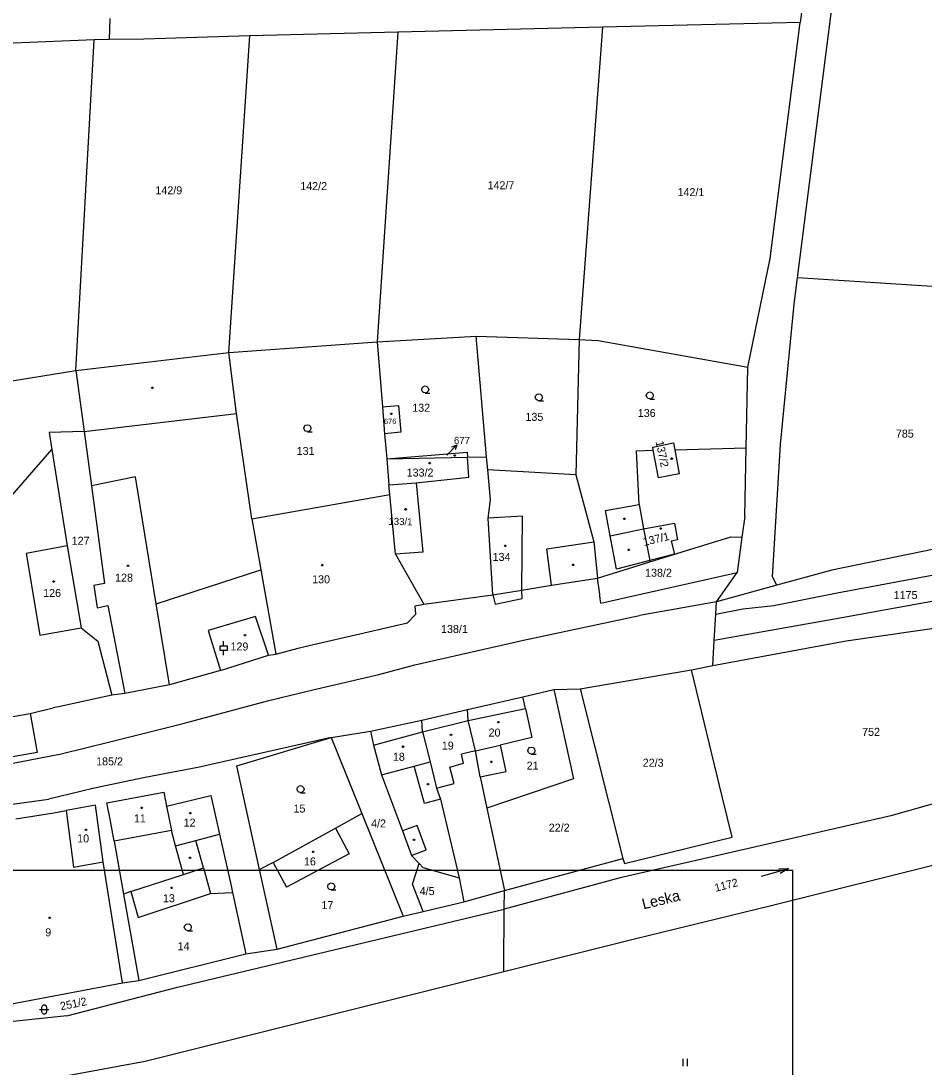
# Model space of a CAD drawing. Extents: x -812394 to -807601, y -1013097 to -1009266.
# Drawn here: x -809610.1 to -809418.3, y -1010812.8 to -1010590.6 of the extents above; entities that cross this region are included whole.
import ezdxf

# ---------------------------------------------------------------- set-up
doc = ezdxf.new("R2010")
doc.units = 0
for name, color, linetype in [('Default', 7, 'Continuous'), ('KN_HRANICE', 7, 'Continuous'), ('KN_KULTURY', 7, 'Continuous'), ('KN_PARCELY', 7, 'Continuous'), ('KN_SLUCKY', 7, 'Continuous'), ('LEGENDA', 7, 'Continuous')]:
    doc.layers.add(name, color=color, linetype=linetype)

# ---------------------------------------------------------------- blocks, each defined once
blk = doc.blocks.new('10292')
at = {"layer": 'Default'}
blk.add_line((0, 3), (0, 0), dxfattribs=at)
blk.add_lwpolyline([(-0.5, 2), (0, 3), (0.5, 2)], dxfattribs=at)
blk = doc.blocks.new('304')
at = {"layer": 'Default'}
blk.add_lwpolyline([(0, 0), (-0.38, 0.1), (-0.65, 0.37), (-0.75, 0.74), (-0.65, 1.11), (-0.38, 1.38), (-0.01, 1.48), (0.36, 1.38), (0.63, 1.11), (0.73, 0.73), (0.63, 0.35), (0.36, 0.08), (-0.02, -0.02), (0.98, -0.02)], dxfattribs=at)
blk = doc.blocks.new('306')
at = {"layer": 'Default'}
for p, q in [((-0.5, 1.5), (-0.5, 0)), ((0.5, 0), (0.5, 1.5))]:
    blk.add_line(p, q, dxfattribs=at)
blk = doc.blocks.new('316')
at = {"layer": 'Default'}
for points in [[(-1, 1), (0.27, 1), (1, 1)], [(-0.5, 1.5), (-0.4, 1.79), (-0.15, 1.97), (0.16, 1.97), (0.41, 1.79), (0.51, 1.5), (0.51, 0.5), (0.41, 0.21), (0.16, 0.03), (-0.15, 0.03), (-0.4, 0.21), (-0.5, 0.5), (-0.5, 1.5)]]:
    blk.add_lwpolyline(points, dxfattribs=at)
blk = doc.blocks.new('NAHRADNI_SYMBOL')
at = {"layer": 'Default'}
blk.add_lwpolyline([(0.09, 0.15), (0.18, 0), (0.09, -0.15), (-0.09, -0.15), (-0.18, 0), (-0.09, 0.15), (0.09, 0.15)], dxfattribs=at)
blk = doc.blocks.new('802')
at = {"layer": 'Default'}
blk.add_line((-3, 0), (3, 0), dxfattribs=at)
blk.add_lwpolyline([(1, 0.5), (3, 0), (1, -0.5)], dxfattribs=at)
blk = doc.blocks.new('318')
at = {"layer": 'Default'}
blk.add_line((0, 2), (0, 3), dxfattribs=at)
blk.add_lwpolyline([(0, 0), (0, 1), (-0.75, 1), (-0.75, 2), (0, 2), (0.75, 2), (0.75, 1), (0, 1)], dxfattribs=at)
blk = doc.blocks.new('402')
at = {"layer": 'Default'}
blk.add_lwpolyline([(0.09, 0.15), (0.18, 0), (0.09, -0.15), (-0.09, -0.15), (-0.18, 0), (-0.09, 0.15), (0.09, 0.15)], dxfattribs=at)

msp = doc.modelspace()

# ---------------------------------------------------------------- linework, layer by layer
at = {"layer": 'KN_HRANICE'}
for p, q in [((-809445.19, -1010645.2), (-809431.77, -1010540.21)), ((-809440.59, -1010560.03), (-809444.6, -1010590.99)), ((-809591.24, -1010590.16), (-809591.38, -1010594.61)), ((-809486.59, -1010592), (-809530.09, -1010593.05)), ((-809486.59, -1010592), (-809491.57, -1010658.3)), ((-809444.6, -1010590.99), (-809486.59, -1010592)), ((-809450.97, -1010641.06), (-809444.6, -1010590.99)), ((-809594.54, -1010594.65), (-809642.04, -1010596.56)), ((-809598.46, -1010664.88), (-809594.54, -1010594.65)), ((-809591.38, -1010594.61), (-809594.54, -1010594.65)), ((-809584.05, -1010594.51), (-809591.38, -1010594.61)), ((-809561.54, -1010593.83), (-809584.05, -1010594.51)), ((-809565.97, -1010661.03), (-809561.54, -1010593.83)), ((-809530.09, -1010593.05), (-809561.54, -1010593.83)), ((-809530.09, -1010593.05), (-809534.45, -1010658.78)), ((-809455.72, -1010664.14), (-809450.97, -1010641.06)), ((-809445.9, -1010650.77), (-809445.19, -1010645.2)), ((-809388.09, -1010648.93), (-809445.19, -1010645.2)), ((-809448.82, -1010680.59), (-809445.9, -1010650.77)), ((-809565.97, -1010661.03), (-809534.45, -1010658.78)), ((-809534.45, -1010658.78), (-809513.45, -1010657.55)), ((-809534.45, -1010658.78), (-809533.33, -1010672.61)), ((-809513.45, -1010657.55), (-809491.57, -1010658.3)), ((-809511.21, -1010683.19), (-809513.45, -1010657.55)), ((-809491.57, -1010658.3), (-809492.27, -1010687)), ((-809491.57, -1010658.3), (-809487.51, -1010658.54)), ((-809487.51, -1010658.54), (-809455.72, -1010664.14)), ((-809598.46, -1010664.88), (-809565.97, -1010661.03)), ((-809564.36, -1010674), (-809565.97, -1010661.03)), ((-809633.83, -1010670.62), (-809598.46, -1010664.88)), ((-809598.46, -1010664.88), (-809596.67, -1010677.83)), ((-809456.08, -1010681.32), (-809455.72, -1010664.14)), ((-809561.08, -1010696.34), (-809564.36, -1010674)), ((-809533.33, -1010672.61), (-809532.87, -1010678.29)), ((-809596.67, -1010677.83), (-809604.12, -1010678.05)), ((-809604.12, -1010678.05), (-809603.55, -1010681.64)), ((-809596.67, -1010677.83), (-809595.14, -1010689.36)), ((-809532.87, -1010678.29), (-809532.44, -1010683.62)), ((-809475.94, -1010681.16), (-809471.53, -1010680.26)), ((-809475.82, -1010681.81), (-809475.94, -1010681.16)), ((-809471.53, -1010680.26), (-809471.26, -1010681.7)), ((-809471.26, -1010681.7), (-809456.08, -1010681.32)), ((-809456.4, -1010695.91), (-809456.08, -1010681.32)), ((-809450.49, -1010708.71), (-809448.82, -1010680.59)), ((-809603.55, -1010681.64), (-809600.29, -1010702.1)), ((-809532.44, -1010683.62), (-809515.29, -1010683.27)), ((-809532.44, -1010683.62), (-809531.99, -1010689.19)), ((-809515.29, -1010683.27), (-809511.21, -1010683.19)), ((-809510.97, -1010685.95), (-809511.21, -1010683.19)), ((-809479.37, -1010681.9), (-809475.82, -1010681.81)), ((-809478.82, -1010693.3), (-809479.37, -1010681.9)), ((-809474.7, -1010687.64), (-809475.82, -1010681.81)), ((-809471.26, -1010681.7), (-809470.29, -1010686.8)), ((-809492.27, -1010687), (-809510.97, -1010685.95)), ((-809510.41, -1010692.32), (-809510.97, -1010685.95)), ((-809492.27, -1010687), (-809488.44, -1010701.23)), ((-809470.29, -1010686.8), (-809474.7, -1010687.64)), ((-809595.14, -1010689.36), (-809592.38, -1010710.12)), ((-809531.99, -1010689.19), (-809526.16, -1010688.74)), ((-809531.79, -1010691.19), (-809531.99, -1010689.19)), ((-809561.08, -1010696.34), (-809531.79, -1010691.19)), ((-809530.54, -1010703.91), (-809531.79, -1010691.19)), ((-809510.85, -1010696.24), (-809510.41, -1010692.32)), ((-809485.94, -1010694.61), (-809478.82, -1010693.3)), ((-809484.96, -1010700.01), (-809485.94, -1010694.61)), ((-809561.08, -1010696.34), (-809559.16, -1010707.24)), ((-809509.86, -1010712.52), (-809510.85, -1010696.24)), ((-809456.4, -1010695.91), (-809456.99, -1010700.24)), ((-809488.44, -1010701.23), (-809487.68, -1010708.94)), ((-809483.66, -1010707.09), (-809484.96, -1010700.01)), ((-809476.51, -1010705.51), (-809459.32, -1010700.23)), ((-809459.32, -1010700.23), (-809456.99, -1010700.24)), ((-809456.99, -1010700.24), (-809458, -1010707.77)), ((-809600.29, -1010702.1), (-809597.34, -1010719.54)), ((-809413.39, -1010702.26), (-809437.86, -1010707.26)), ((-809530.54, -1010703.91), (-809524.53, -1010714.47)), ((-809487.68, -1010708.94), (-809476.51, -1010705.51)), ((-809476.56, -1010705.21), (-809483.66, -1010707.09)), ((-809476.56, -1010705.21), (-809476.51, -1010705.51)), ((-809581.39, -1010714.41), (-809559.16, -1010707.24)), ((-809559.16, -1010707.24), (-809556, -1010725.11)), ((-809481.63, -1010713.11), (-809458, -1010707.77)), ((-809462.39, -1010714.03), (-809458, -1010707.77)), ((-809437.86, -1010707.26), (-809449.57, -1010710.49)), ((-809592.38, -1010710.12), (-809594.66, -1010710.54)), ((-809497.45, -1010710.44), (-809487.68, -1010708.94)), ((-809487.2, -1010712.35), (-809487.68, -1010708.94)), ((-809449.57, -1010710.49), (-809450.49, -1010708.71)), ((-809594.66, -1010710.54), (-809593.93, -1010715.27)), ((-809524.53, -1010714.47), (-809509.86, -1010712.52)), ((-809509.86, -1010712.52), (-809509.39, -1010714.47)), ((-809503.76, -1010711.54), (-809497.45, -1010710.44)), ((-809503.65, -1010713.32), (-809503.76, -1010711.54)), ((-809487.15, -1010712.67), (-809487.2, -1010712.35)), ((-809449.57, -1010710.49), (-809462.39, -1010714.03)), ((-809578.59, -1010731.65), (-809581.39, -1010714.41)), ((-809526.41, -1010714.85), (-809524.53, -1010714.47)), ((-809509.39, -1010714.47), (-809503.65, -1010713.32)), ((-809487.06, -1010713.28), (-809487.15, -1010712.67)), ((-809486.99, -1010713.83), (-809487.06, -1010713.28)), ((-809486.92, -1010714.3), (-809486.99, -1010713.83)), ((-809486.92, -1010714.3), (-809481.63, -1010713.11)), ((-809462.39, -1010714.03), (-809471.53, -1010715.63)), ((-809462.54, -1010716.59), (-809462.39, -1010714.03)), ((-809593.93, -1010715.27), (-809591.65, -1010714.79)), ((-809591.65, -1010714.79), (-809588.06, -1010733.47)), ((-809528.01, -1010718.45), (-809526.26, -1010716.6)), ((-809526.26, -1010716.6), (-809526.41, -1010714.85)), ((-809503.35, -1010722.13), (-809478.73, -1010716.9)), ((-809471.53, -1010715.63), (-809478.73, -1010716.9)), ((-809462.86, -1010722.22), (-809462.54, -1010716.59)), ((-809434.83, -1010722.26), (-809386.46, -1010715.35)), ((-809549.8, -1010723.5), (-809528.01, -1010718.45)), ((-809597.34, -1010719.54), (-809593.76, -1010722.34)), ((-809593.76, -1010722.34), (-809590.8, -1010733.81)), ((-809551.26, -1010723.86), (-809549.8, -1010723.5)), ((-809526.46, -1010727.38), (-809503.35, -1010722.13)), ((-809463.16, -1010727.52), (-809462.86, -1010722.22)), ((-809463.16, -1010727.52), (-809434.83, -1010722.26)), ((-809567.73, -1010728.55), (-809557.57, -1010725.36)), ((-809557.57, -1010725.36), (-809556, -1010725.11)), ((-809556, -1010725.11), (-809551.26, -1010723.86)), ((-809534.09, -1010729.46), (-809526.46, -1010727.38)), ((-809467.68, -1010728.42), (-809463.16, -1010727.52)), ((-809567.73, -1010728.55), (-809578.59, -1010731.65)), ((-809548.16, -1010732.72), (-809534.09, -1010729.46)), ((-809491.31, -1010732.5), (-809467.68, -1010728.42)), ((-809578.59, -1010731.65), (-809588.06, -1010733.47)), ((-809496.94, -1010732.6), (-809491.31, -1010732.5)), ((-809491.31, -1010732.5), (-809482.31, -1010768.54)), ((-809590.8, -1010733.81), (-809601.82, -1010736.22)), ((-809588.06, -1010733.47), (-809590.8, -1010733.81)), ((-809557.49, -1010734.93), (-809548.16, -1010732.72)), ((-809515.24, -1010736.89), (-809503.51, -1010734.14)), ((-809503.51, -1010734.14), (-809496.94, -1010732.6)), ((-809502.98, -1010736.65), (-809503.51, -1010734.14)), ((-809496.94, -1010732.6), (-809492.77, -1010751.6)), ((-809608.17, -1010737.7), (-809603.28, -1010736.54)), ((-809601.82, -1010736.22), (-809603.28, -1010736.54)), ((-809575.93, -1010739.9), (-809557.49, -1010734.93)), ((-809524.96, -1010739.16), (-809515.24, -1010736.89)), ((-809515.12, -1010739.21), (-809515.24, -1010736.89)), ((-809502.98, -1010736.65), (-809501.59, -1010742.84)), ((-809618.66, -1010739.51), (-809608.17, -1010737.7)), ((-809608.17, -1010737.7), (-809606.66, -1010745.99)), ((-809535.88, -1010741.49), (-809524.96, -1010739.16)), ((-809524.82, -1010741.63), (-809524.96, -1010739.16)), ((-809513.6, -1010745.64), (-809515.12, -1010739.21)), ((-809591.21, -1010743.76), (-809575.93, -1010739.9)), ((-809544.23, -1010742.79), (-809572.56, -1010749.19)), ((-809564.25, -1010748.81), (-809544.23, -1010742.79)), ((-809544.23, -1010742.79), (-809535.88, -1010741.49)), ((-809544.23, -1010742.79), (-809537.7, -1010758.97)), ((-809535.88, -1010741.49), (-809535.22, -1010744.44)), ((-809524.82, -1010741.63), (-809523.2, -1010747.95)), ((-809501.59, -1010742.84), (-809508.37, -1010744.41)), ((-809601.6, -1010746.29), (-809591.21, -1010743.76)), ((-809535.22, -1010744.44), (-809533.52, -1010750.77)), ((-809512.59, -1010751.13), (-809513.6, -1010745.64)), ((-809508.37, -1010744.41), (-809507.14, -1010750.01)), ((-809606.66, -1010745.99), (-809626.64, -1010749.55)), ((-809621.25, -1010750.05), (-809601.6, -1010746.29)), ((-809523.2, -1010747.95), (-809521.85, -1010753.55)), ((-809572.56, -1010749.19), (-809583.73, -1010751.27)), ((-809559.42, -1010770.87), (-809564.25, -1010748.81)), ((-809512.59, -1010751.13), (-809507.14, -1010750.01)), ((-809583.73, -1010751.27), (-809594.82, -1010753.62)), ((-809533.52, -1010750.77), (-809529.09, -1010762.64)), ((-809512.59, -1010751.13), (-809511.16, -1010757.85)), ((-809492.77, -1010751.6), (-809511.16, -1010757.85)), ((-809594.82, -1010753.62), (-809604.22, -1010755.92)), ((-809591.91, -1010756.66), (-809579.76, -1010754.43)), ((-809579.76, -1010754.43), (-809579.19, -1010757.38)), ((-809521.85, -1010753.55), (-809521.03, -1010755.88)), ((-809619.48, -1010758), (-809604.22, -1010755.92)), ((-809591.2, -1010760.14), (-809591.91, -1010756.66)), ((-809579.19, -1010757.38), (-809569.76, -1010755.12)), ((-809569.76, -1010755.12), (-809567.94, -1010763.34)), ((-809521.03, -1010755.88), (-809517.06, -1010772.62)), ((-809611.19, -1010760.06), (-809603.15, -1010758.78)), ((-809603.15, -1010758.78), (-809600.5, -1010758.29)), ((-809594.29, -1010757.19), (-809600.5, -1010758.29)), ((-809600.5, -1010758.29), (-809598.99, -1010770.33)), ((-809592.64, -1010769.19), (-809594.29, -1010757.19)), ((-809579.19, -1010757.38), (-809578.18, -1010762.54)), ((-809543.29, -1010762.05), (-809537.7, -1010758.97)), ((-809537.7, -1010758.97), (-809528.91, -1010780.74)), ((-809511.16, -1010757.85), (-809507.45, -1010775.29)), ((-809590.34, -1010764.82), (-809591.2, -1010760.14)), ((-809577.28, -1010765.78), (-809578.18, -1010762.54)), ((-809572.99, -1010764.66), (-809567.94, -1010763.34)), ((-809567.94, -1010763.34), (-809565.5, -1010774.33)), ((-809556.56, -1010769.35), (-809543.29, -1010762.05)), ((-809543.29, -1010762.05), (-809540.4, -1010767.48)), ((-809529.09, -1010762.64), (-809527.15, -1010767.85)), ((-809590.34, -1010764.82), (-809588.33, -1010776.05)), ((-809577.28, -1010765.78), (-809572.99, -1010764.66)), ((-809575.59, -1010771.87), (-809577.28, -1010765.78)), ((-809481.91, -1010769.54), (-809459.07, -1010763.94)), ((-809540.4, -1010767.48), (-809553.7, -1010774.56)), ((-809527.15, -1010767.85), (-809525.51, -1010769.54)), ((-809598.99, -1010770.33), (-809592.64, -1010769.19)), ((-809588.54, -1010794.9), (-809592.64, -1010769.19)), ((-809556.56, -1010769.35), (-809559.42, -1010770.87)), ((-809556.56, -1010769.35), (-809553.7, -1010774.56)), ((-809526.96, -1010773.94), (-809525.51, -1010769.54)), ((-809525.51, -1010769.54), (-809524.78, -1010770.4)), ((-809507.45, -1010775.29), (-809482.31, -1010768.54)), ((-809482.31, -1010768.54), (-809481.91, -1010769.54)), ((-809450.75, -1010778.5), (-809413.92, -1010769.26)), ((-809586.77, -1010775.53), (-809575.59, -1010771.87)), ((-809555.73, -1010787.74), (-809559.42, -1010770.87)), ((-809524.78, -1010770.4), (-809517.06, -1010772.62)), ((-809565.5, -1010774.33), (-809565.19, -1010775.74)), ((-809524.66, -1010779.77), (-809526.96, -1010773.94)), ((-809517.06, -1010772.62), (-809516.02, -1010777.68)), ((-809586.77, -1010775.53), (-809588.33, -1010776.05)), ((-809588.33, -1010776.05), (-809585.11, -1010794.39)), ((-809586.77, -1010775.53), (-809585.25, -1010781)), ((-809585.25, -1010781), (-809569.85, -1010775.96)), ((-809569.85, -1010775.96), (-809565.19, -1010775.74)), ((-809565.19, -1010775.74), (-809562.33, -1010788.78)), ((-809516.02, -1010777.68), (-809507.45, -1010775.29)), ((-809507.48, -1010779.27), (-809507.45, -1010775.29)), ((-809524.66, -1010779.77), (-809516.02, -1010777.68)), ((-809479.79, -1010785.54), (-809450.75, -1010778.5)), ((-809576.87, -1010795.8), (-809507.48, -1010779.27)), ((-809555.73, -1010787.74), (-809528.91, -1010780.74)), ((-809528.91, -1010780.74), (-809524.66, -1010779.77)), ((-809507.51, -1010783.2), (-809507.48, -1010779.27)), ((-809507.54, -1010787.61), (-809507.51, -1010783.2)), ((-809507.57, -1010792.49), (-809479.79, -1010785.54)), ((-809562.33, -1010788.78), (-809555.73, -1010787.74)), ((-809507.57, -1010792.49), (-809507.54, -1010787.61)), ((-809585.11, -1010794.39), (-809562.33, -1010788.78)), ((-809583.77, -1010811.56), (-809507.57, -1010792.49)), ((-809588.54, -1010794.9), (-809585.11, -1010794.39)), ((-809615.96, -1010800.09), (-809588.54, -1010794.9)), ((-809600.38, -1010801.89), (-809576.87, -1010795.8)), ((-809600.38, -1010801.89), (-809643.49, -1010806.47)), ((-809609.07, -1010816.23), (-809583.77, -1010811.56))]:
    msp.add_line(p, q, dxfattribs=at)
for points in [[(-809533.33, -1010672.61), (-809529.94, -1010672.33), (-809529.46, -1010677.99), (-809532.87, -1010678.29)], [(-809623.13, -1010728.35), (-809625.78, -1010708.61), (-809623.83, -1010704.87), (-809603.55, -1010681.64)], [(-809532.44, -1010683.62), (-809515.36, -1010682.23), (-809515.29, -1010683.27)], [(-809526.16, -1010688.74), (-809514.99, -1010687.55), (-809515.29, -1010683.27)], [(-809386.86, -1010717.18), (-809390.64, -1010734.74), (-809392.82, -1010743.13), (-809395.75, -1010747.43), (-809400.98, -1010751.89), (-809410.38, -1010755.21), (-809425.36, -1010759.45), (-809455.87, -1010766.45), (-809482.83, -1010772.6), (-809507.48, -1010779.27)], [(-809459.07, -1010763.94), (-809461.16, -1010755.31), (-809467.68, -1010728.42)]]:
    msp.add_lwpolyline(points, dxfattribs=at)
at = {"layer": 'KN_SLUCKY'}
for p, q in [((-809596.67, -1010677.83), (-809564.36, -1010674)), ((-809585.78, -1010687.46), (-809595.14, -1010689.36)), ((-809581.39, -1010714.41), (-809585.78, -1010687.46)), ((-809526.16, -1010688.74), (-809524.76, -1010703.42)), ((-809478.82, -1010693.3), (-809477.86, -1010698.52)), ((-809503.61, -1010695.79), (-809510.85, -1010696.24)), ((-809503.76, -1010711.54), (-809503.61, -1010695.79)), ((-809484.96, -1010700.01), (-809477.86, -1010698.52)), ((-809477.86, -1010698.52), (-809471.32, -1010697.32)), ((-809477.86, -1010698.52), (-809476.56, -1010705.21)), ((-809471.32, -1010697.32), (-809470.68, -1010700.85)), ((-809498.4, -1010702.75), (-809488.44, -1010701.23)), ((-809470.68, -1010700.85), (-809472.02, -1010701.1)), ((-809472.02, -1010701.1), (-809471.31, -1010703.88)), ((-809600.29, -1010702.1), (-809609, -1010703.76)), ((-809524.76, -1010703.42), (-809530.54, -1010703.91)), ((-809497.45, -1010710.44), (-809498.4, -1010702.75)), ((-809609, -1010703.76), (-809606.14, -1010721.1)), ((-809471.31, -1010703.88), (-809476.56, -1010705.21)), ((-809509.86, -1010712.52), (-809503.76, -1010711.54)), ((-809560.3, -1010717.14), (-809570.39, -1010720.06)), ((-809557.57, -1010725.36), (-809560.3, -1010717.14)), ((-809606.14, -1010721.1), (-809597.34, -1010719.54)), ((-809570.39, -1010720.06), (-809567.73, -1010728.55)), ((-809515.12, -1010739.21), (-809502.98, -1010736.65)), ((-809524.82, -1010741.63), (-809515.12, -1010739.21)), ((-809535.22, -1010744.44), (-809524.82, -1010741.63)), ((-809513.6, -1010745.64), (-809516.56, -1010746.35)), ((-809513.6, -1010745.64), (-809508.37, -1010744.41)), ((-809526.63, -1010748.89), (-809523.2, -1010747.95)), ((-809516.09, -1010748.24), (-809516.56, -1010746.35)), ((-809533.52, -1010750.77), (-809526.63, -1010748.89)), ((-809524.42, -1010756.83), (-809526.63, -1010748.89)), ((-809519.06, -1010749.09), (-809516.09, -1010748.24)), ((-809518.14, -1010752.55), (-809519.06, -1010749.09)), ((-809521.85, -1010753.55), (-809518.14, -1010752.55)), ((-809521.03, -1010755.88), (-809524.42, -1010756.83)), ((-809578.18, -1010762.54), (-809590.34, -1010764.82)), ((-809525.94, -1010761.52), (-809529.09, -1010762.64)), ((-809524.07, -1010766.63), (-809525.94, -1010761.52)), ((-809571.37, -1010770.49), (-809572.99, -1010764.66)), ((-809527.15, -1010767.85), (-809524.07, -1010766.63)), ((-809575.59, -1010771.87), (-809571.37, -1010770.49)), ((-809571.37, -1010770.49), (-809569.85, -1010775.96))]:
    msp.add_line(p, q, dxfattribs=at)
for points in [[(-809462.54, -1010716.59), (-809456.78, -1010715.47), (-809450.24, -1010714.77), (-809436.78, -1010712.1), (-809413.21, -1010707.7), (-809386.06, -1010702.58)], [(-809385.19, -1010708.29), (-809412.36, -1010713.13), (-809435.74, -1010717.37), (-809462.86, -1010722.22)]]:
    msp.add_lwpolyline(points, dxfattribs=at)
at = {"layer": 'LEGENDA'}
msp.add_lwpolyline([(-810040.19, -1011191.03), (-809446.19, -1011191.03), (-809446.19, -1010771.03), (-810040.19, -1010771.03)], close=True, dxfattribs=at)

# ---------------------------------------------------------------- block references
at = {"layer": 'KN_KULTURY'}
for name, p in [('402', (-809582.2, -1010668.57)), ('304', (-809524.25, -1010669.64)), ('304', (-809500.12, -1010671.31)), ('304', (-809476.55, -1010670.92)), ('402', (-809531.46, -1010674.08)), ('304', (-809549.27, -1010677.86)), ('402', (-809517.99, -1010682.9)), ('402', (-809471.88, -1010683.59)), ('402', (-809523.3, -1010684.54)), ('402', (-809528.4, -1010694.35)), ('402', (-809481.95, -1010696.36)), ('402', (-809474.22, -1010698.43)), ('402', (-809507.27, -1010702.09)), ('402', (-809481.01, -1010702.97)), ('402', (-809587.39, -1010706.38)), ('NAHRADNI_SYMBOL', (-809546.13, -1010706.21)), ('402', (-809492.83, -1010706.14)), ('402', (-809603.18, -1010709.67)), ('402', (-809562.55, -1010721.09)), ('318', (-809567.07, -1010725.36)), ('402', (-809508.71, -1010739.53)), ('402', (-809518.76, -1010742.26)), ('402', (-809528.95, -1010744.75)), ('304', (-809501.69, -1010746.34)), ('402', (-809510.19, -1010747.99)), ('304', (-809550.72, -1010754.51)), ('402', (-809523.65, -1010752.72)), ('402', (-809584.45, -1010757.72)), ('NAHRADNI_SYMBOL', (-809574.13, -1010758.87)), ('402', (-809596.3, -1010762.41)), ('402', (-809526.65, -1010764.55)), ('402', (-809548.06, -1010767.1)), ('402', (-809574.2, -1010768.35)), ('402', (-809578.14, -1010774.75)), ('304', (-809544.19, -1010775.16)), ('NAHRADNI_SYMBOL', (-809604.01, -1010781.1)), ('304', (-809574.67, -1010783.84)), ('316', (-809605.18, -1010801.57)), ('306', (-809469.01, -1010812.57))]:
    msp.add_blockref(name, p, dxfattribs=at)
at = {"layer": 'KN_KULTURY', "rotation": 15.527156}
msp.add_blockref('802', (-809449.95, -1010771.45), dxfattribs=at)
at = {"layer": 'KN_PARCELY', "rotation": -43.72729700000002}
msp.add_blockref('10292', (-809519.64, -1010682.85), dxfattribs=at)

# ---------------------------------------------------------------- texts
at = {"layer": 'KN_PARCELY'}
for s, height, p in [('142/9', 1.7, (-809581.56, -1010627.46)), ('142/2', 1.7, (-809550.79, -1010626.56)), ('142/7', 1.7, (-809511.01, -1010626.39)), ('142/1', 1.7, (-809470.66, -1010627.85)), ('132', 1.7, (-809527.01, -1010673.64)), ('135', 1.7, (-809502.96, -1010675.57)), ('136', 1.7, (-809479.1, -1010674.75)), ('785', 1.7, (-809424.28, -1010679.13)), ('131', 1.7, (-809551.56, -1010682.81)), ('677', 0.1, (-809519.62, -1010682.95)), ('133/2', 1.7, (-809528.19, -1010687.4)), ('127', 1.7, (-809599.35, -1010701.88)), ('134', 1.7, (-809509.94, -1010705.31)), ('128', 1.7, (-809590.12, -1010709.72)), ('138/2', 1.7, (-809477.55, -1010708.67)), ('130', 1.7, (-809548.27, -1010710.06)), ('126', 1.7, (-809605.4, -1010712.97)), ('1175', 1.7, (-809424.75, -1010713.41)), ('138/1', 1.7, (-809520.89, -1010720.62)), ('129', 1.7, (-809565.61, -1010724.33)), ('20', 1.7, (-809510.8, -1010742.61)), ('752', 1.7, (-809431.45, -1010742.46)), ('19', 1.7, (-809520.73, -1010745.38)), ('185/2', 1.7, (-809594.15, -1010748.73)), ('18', 1.7, (-809531.12, -1010747.76)), ('21', 1.7, (-809502.71, -1010749.63)), ('22/3', 1.7, (-809478.05, -1010749.02)), ('11', 1.7, (-809586.13, -1010760.85)), ('15', 1.7, (-809552.23, -1010758.74)), ('12', 1.7, (-809575.57, -1010761.74)), ('4/2', 1.7, (-809535.74, -1010761.91)), ('22/2', 1.7, (-809498.01, -1010762.81)), ('10', 1.7, (-809598.18, -1010765.09)), ('16', 1.7, (-809550.01, -1010769.97)), ('4/5', 1.7, (-809525.44, -1010776.27)), ('13', 1.7, (-809579.96, -1010777.79)), ('17', 1.7, (-809546.3, -1010779.25)), ('9', 1.7, (-809604.96, -1010785.03)), ('14', 1.7, (-809576.84, -1010787.98))]:
    msp.add_text(s, height=height, dxfattribs=at).set_placement(p)
for s, height, rotation, p in [('676', 1.14, 0.401, (-809533.01, -1010676.24)), ('677', 1.52, 359.015, (-809518.16, -1010680.47)), ('137/2', 1.7, 281.838, (-809475.33, -1010680)), ('133/1', 1.52, 358.672, (-809532.07, -1010697.65)), ('137/1', 1.7, 13.407, (-809477.79, -1010702.15)), ('1172', 1.7, 14.324, (-809462.56, -1010775.58)), ('Leska', 2.3, 13.808, (-809477.9, -1010779.33)), ('251/2', 1.7, 11.574, (-809601.6, -1010800.76))]:
    msp.add_text(s, height=height, rotation=rotation, dxfattribs=at).set_placement(p)

doc.saveas('drawing.dxf')
